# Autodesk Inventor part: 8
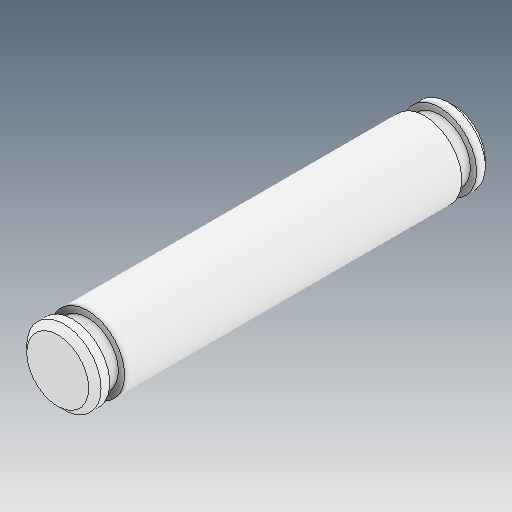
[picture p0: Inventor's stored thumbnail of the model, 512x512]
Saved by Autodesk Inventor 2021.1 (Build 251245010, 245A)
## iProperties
Created: 2021-06
Part Number: 8
Material: Ogólny
Document SubType Name: Modeling
Designer: user
Density: 1 g/cm^3
Appearance: Domyślna
Author: user
Revision Number: ÈÎºÎ
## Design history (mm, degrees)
feature "ÊäÈë1"
node "Bryła1"
